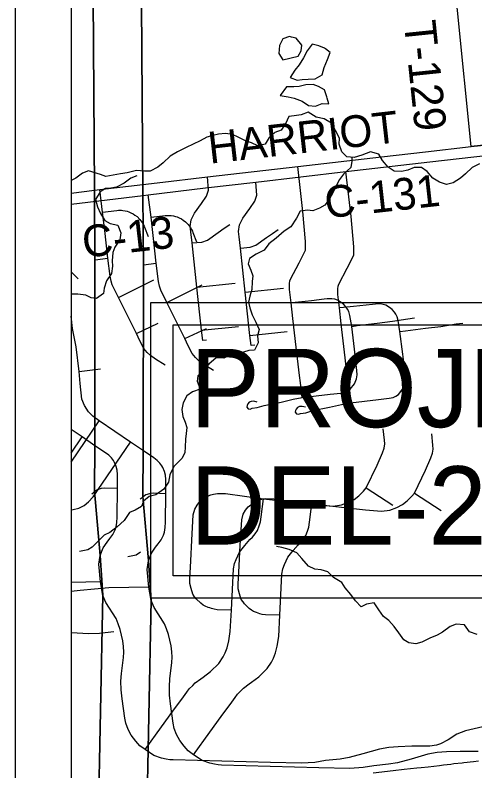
# Model space of a CAD drawing. Extents: x -38.2 to 41.9, y -4 to 24.9.
# Drawn here: x 2 to 2.823, y 17.256 to 18.608 of the extents above; entities that cross this region are included whole.
import ezdxf

# ---------------------------------------------------------------- set-up
doc = ezdxf.new("R2010")
doc.units = 0
for name, color, linetype in [('Default', 7, 'Continuous'), ('GM_X_County_Road', 7, 'Continuous'), ('GM_X_County_Road_Text', 7, 'Continuous'), ('GM_X_Interchange_Ramps', 7, 'Continuous'), ('GM_X_Minor_Lake', 7, 'Continuous'), ('GM_X_Minor_River', 7, 'Continuous'), ('GM_X_Minor_River_Text', 7, 'Continuous'), ('GM_X_State_Location', 7, 'Continuous'), ('GM_X_Township_Road', 7, 'Continuous'), ('GM_X_Township_Road_Text', 7, 'Continuous'), ('GM_X_Township_Text', 7, 'Continuous'), ('SH_Border', 7, 'Continuous'), ('SH_Cut_Line', 7, 'Continuous'), ('SH_Data', 7, 'Continuous'), ('SH_Text', 7, 'Continuous')]:
    doc.layers.add(name, color=color, linetype=linetype)

msp = doc.modelspace()

# ---------------------------------------------------------------- linework, layer by layer
at = {"layer": 'Default'}
msp.add_lwpolyline([(2.8287, 17.2735), (2.82, 17.2725), (2.8029, 17.2705), (2.7997, 17.2701), (2.785, 17.2684), (2.7794, 17.2677), (2.7662, 17.2662), (2.759, 17.2654), (2.7387, 17.263), (2.7266, 17.2616), (2.7184, 17.2607), (2.6958, 17.2583), (2.6765, 17.2561), (2.6404, 17.252)], dxfattribs=at)
at = {"layer": 'GM_X_County_Road'}
msp.add_line((2.1, 18.2896), (2.1423, 18.2947), dxfattribs=at)
for points in [[(2.1423, 18.2947), (2.1516, 18.2959), (2.2543, 18.308), (2.3444, 18.3185), (2.5055, 18.3373), (2.6552, 18.3545), (2.734, 18.3635), (2.8156, 18.3728)], [(2.8156, 18.3728), (2.8545, 18.3772), (2.8608, 18.3772), (2.8641, 18.3768), (2.8674, 18.3761), (2.8706, 18.375), (2.8767, 18.3722), (2.8852, 18.3671), (2.9348, 18.3318), (2.9748, 18.3043)]]:
    msp.add_lwpolyline(points, dxfattribs=at)
at = {"layer": 'GM_X_Interchange_Ramps'}
for points in [[(2.1, 20.4515), (2.1, 14.1636), (2.1303, 14.1626), (2.1303, 14.1722), (2.1335, 15.4167), (2.1334, 15.4951), (2.1328, 15.831), (2.1521, 16.6664), (2.1489, 17.073), (2.1485, 17.1357), (2.1484, 17.1455), (2.1486, 17.1556), (2.1569, 17.5704), (2.1549, 17.5972), (2.1521, 17.6416), (2.1422, 17.7563), (2.1427, 17.838), (2.1429, 18.1709), (2.1421, 18.2952), (2.138, 18.8976), (2.1339, 19.396), (2.1223, 20.2725), (2.1124, 20.4526)], [(2.1, 20.4344), (2.1, 14.1575), (2.2168, 14.1534), (2.2168, 14.163), (2.22, 15.4075), (2.2199, 15.4859), (2.2193, 15.8218), (2.2386, 16.6572), (2.2354, 17.0638), (2.235, 17.1266), (2.2349, 17.1363), (2.2351, 17.1464), (2.2434, 17.5612), (2.2414, 17.5881), (2.2386, 17.6324), (2.2287, 17.7471), (2.2291, 17.8288), (2.2294, 18.1617), (2.2286, 18.286), (2.2245, 18.8884), (2.2204, 19.3868), (2.2088, 20.2633), (2.1989, 20.4434)]]:
    msp.add_lwpolyline(points, close=True, dxfattribs=at)
for points in [[(2.1223, 20.2725), (2.1339, 19.396), (2.138, 18.8976), (2.1421, 18.2952), (2.1429, 18.1709), (2.1427, 17.838), (2.1422, 17.7563), (2.1521, 17.6416), (2.1549, 17.5972), (2.1569, 17.5704), (2.1486, 17.1556)], [(2.2088, 20.2633), (2.2204, 19.3868), (2.2245, 18.8884), (2.2286, 18.286), (2.2294, 18.1617), (2.2291, 17.8288), (2.2287, 17.7471), (2.2386, 17.6324), (2.2414, 17.5881), (2.2434, 17.5612), (2.2351, 17.1464)]]:
    msp.add_lwpolyline(points, dxfattribs=at)
at = {"layer": 'GM_X_Minor_Lake'}
for points in [[(2.4947, 18.5687), (2.4909, 18.5697), (2.4791, 18.5656), (2.473, 18.5538), (2.4718, 18.5394), (2.479, 18.528)], [(2.479, 18.528), (2.5063, 18.5344), (2.5117, 18.5438), (2.5132, 18.5541), (2.503, 18.5666), (2.4947, 18.5687)], [(2.5552, 18.5474), (2.5534, 18.5487), (2.5432, 18.5529), (2.5315, 18.5559), (2.5227, 18.5438), (2.5162, 18.5317), (2.5082, 18.5188), (2.5006, 18.5093), (2.4922, 18.4961)], [(2.4922, 18.4961), (2.5043, 18.4919), (2.5138, 18.4926), (2.5241, 18.4937), (2.537, 18.4941), (2.5491, 18.5012), (2.5526, 18.5145), (2.5591, 18.5285), (2.5637, 18.5414), (2.5552, 18.5474)], [(2.5584, 18.4592), (2.5578, 18.4617), (2.5536, 18.4743), (2.5426, 18.48), (2.5331, 18.4838), (2.5202, 18.4835), (2.5081, 18.4805), (2.4986, 18.4794), (2.4853, 18.4798), (2.4739, 18.4639)], [(2.4739, 18.4639), (2.4887, 18.4619), (2.4993, 18.4593), (2.5133, 18.4539), (2.5251, 18.4463), (2.5372, 18.4451), (2.549, 18.4496), (2.5611, 18.4492), (2.5584, 18.4592)]]:
    msp.add_lwpolyline(points, dxfattribs=at)
at = {"layer": 'GM_X_Minor_River'}
for points in [[(2.7593, 18.309), (2.7472, 18.3166), (2.7373, 18.3284), (2.7267, 18.3353), (2.7138, 18.3353), (2.7024, 18.3308), (2.6914, 18.3281), (2.6781, 18.3289), (2.6671, 18.3362), (2.6573, 18.348), (2.6505, 18.359), (2.6357, 18.3636), (2.6201, 18.3576), (2.6068, 18.3534), (2.5935, 18.3542), (2.5844, 18.3637), (2.5799, 18.377), (2.5803, 18.3881), (2.5732, 18.4017), (2.566, 18.4147), (2.5527, 18.4227), (2.5383, 18.4257), (2.5243, 18.4341), (2.5117, 18.4296), (2.4992, 18.4278), (2.4897, 18.4266), (2.484, 18.4134), (2.476, 18.4024), (2.4646, 18.3983), (2.4547, 18.3892), (2.4471, 18.3774), (2.4341, 18.374), (2.4231, 18.3794), (2.4121, 18.3832), (2.3993, 18.3897), (2.389, 18.3947), (2.3761, 18.3962), (2.364, 18.3951), (2.3537, 18.3925), (2.3431, 18.3895), (2.3313, 18.3831), (2.3187, 18.3774), (2.3058, 18.3714), (2.2902, 18.3635), (2.2773, 18.3555), (2.2647, 18.3438), (2.2552, 18.3362), (2.2415, 18.3291), (2.2313, 18.3287), (2.2172, 18.3299), (2.2005, 18.3261), (2.1884, 18.3243), (2.1625, 18.319), (2.1527, 18.3229), (2.1315, 18.3294)], [(2.6024, 18.3537), (2.6026, 18.347), (2.6003, 18.3352), (2.5874, 18.3235), (2.5805, 18.3137), (2.574, 18.3015), (2.569, 18.2913), (2.5618, 18.278), (2.5542, 18.2682), (2.5447, 18.2629), (2.5325, 18.258), (2.523, 18.2588), (2.5101, 18.2573), (2.5036, 18.2448), (2.4933, 18.2293), (2.4815, 18.2217), (2.4671, 18.2088), (2.4538, 18.1986), (2.4458, 18.1876), (2.4313, 18.1805), (2.4195, 18.1729), (2.4172, 18.1631), (2.4214, 18.1517), (2.4251, 18.1418), (2.4243, 18.1312), (2.4232, 18.1171), (2.4201, 18.105), (2.4174, 18.0947), (2.42, 18.0845), (2.4238, 18.0716), (2.4306, 18.0586), (2.4363, 18.0457), (2.4339, 18.0343), (2.4347, 18.0218), (2.4282, 18.0089), (2.4183, 18.0078), (2.4084, 18.0048), (2.3985, 18.0014), (2.3864, 18.0011), (2.3731, 17.9946), (2.3598, 17.9947), (2.3465, 17.9837), (2.3381, 17.9739), (2.3267, 17.9629), (2.3259, 17.9534), (2.3312, 17.939), (2.3171, 17.9341), (2.3072, 17.9269), (2.3007, 17.9144), (2.298, 17.9026), (2.3003, 17.8901), (2.3044, 17.8798), (2.3071, 17.8703), (2.3063, 17.8593), (2.3051, 17.8494), (2.3043, 17.835), (2.3035, 17.8255), (2.2986, 17.8157), (2.2837, 17.8005), (2.2768, 17.7857), (2.2742, 17.7728), (2.2658, 17.76), (2.2517, 17.7501), (2.2399, 17.7471), (2.2296, 17.7388), (2.2262, 17.729), (2.2148, 17.7222), (2.2045, 17.7184), (2.195, 17.704), (2.1828, 17.6926), (2.1695, 17.6824), (2.1596, 17.6775), (2.1379, 17.6565)], [(2.8308, 18.3418), (2.8174, 18.3354), (2.806, 18.324), (2.7965, 18.3161), (2.7836, 18.3078), (2.7718, 18.3051), (2.7593, 18.309)], [(2.1315, 18.3294), (2.1203, 18.3255), (2.1085, 18.3164), (2.1, 18.3122)], [(2.1379, 17.6565), (2.1301, 17.6514), (2.1154, 17.6484)], [(2.5247, 17.6221), (2.5129, 17.6358), (2.5042, 17.6461), (2.4902, 17.6519), (2.4773, 17.6557), (2.4674, 17.6572)], [(2.8265, 17.5001), (2.8129, 17.5047), (2.8038, 17.5173), (2.789, 17.5185), (2.7784, 17.5143), (2.7647, 17.5045), (2.7548, 17.4988), (2.7419, 17.4936), (2.7278, 17.4864), (2.7171, 17.4834), (2.7046, 17.4849), (2.6951, 17.4903), (2.6864, 17.5028), (2.6781, 17.5146), (2.6687, 17.5249), (2.6592, 17.5321), (2.6509, 17.5439), (2.6422, 17.5565), (2.6285, 17.5543), (2.619, 17.5497), (2.6092, 17.5604), (2.6005, 17.5718), (2.5902, 17.5836), (2.5842, 17.5931), (2.5694, 17.6019), (2.5596, 17.6122), (2.5474, 17.6156), (2.536, 17.6172), (2.5247, 17.6221)]]:
    msp.add_lwpolyline(points, dxfattribs=at)
at = {"layer": 'GM_X_Minor_River_Text'}
for points in [[(2.218, 18.3203), (2.2068, 18.3163), (2.195, 18.3072), (2.1813, 18.3004), (2.1715, 18.2985), (2.1616, 18.2978), (2.1521, 18.2917), (2.1441, 18.2781), (2.1475, 18.2652), (2.1528, 18.2534), (2.1607, 18.2405), (2.1702, 18.2351), (2.1835, 18.2325), (2.1891, 18.2188), (2.1872, 18.2059), (2.1781, 18.193), (2.1747, 18.1831), (2.1739, 18.1683), (2.1742, 18.1588), (2.1727, 18.1459), (2.1632, 18.1327), (2.1593, 18.1198), (2.1582, 18.1099), (2.1457, 18.1012), (2.1358, 18.102), (2.1263, 18.1069), (2.1123, 18.1088), (2.1, 18.1089)], [(2.2244, 17.6473), (2.2165, 17.6422), (2.2019, 17.6392)]]:
    msp.add_lwpolyline(points, dxfattribs=at)
at = {"layer": 'GM_X_State_Location'}
for p, q in [((2.2296, 18.1612), (2.2522, 18.1641)), ((2.113, 18.1364), (2.1, 18.149)), ((2.2712, 18.0938), (2.3346, 18.1254)), ((2.4115, 18.1123), (2.4802, 18.1195)), ((2.3034, 18.0293), (2.3424, 18.0477)), ((2.4199, 18.0351), (2.4864, 18.0419)), ((2.1146, 17.9706), (2.1526, 17.9751)), ((2.1, 17.8085), (2.1502, 17.8822)), ((2.7147, 17.7531), (2.7624, 17.7219)), ((2.2237, 17.7425), (2.2289, 17.7465))]:
    msp.add_line(p, q, dxfattribs=at)
for points in [[(2.5999, 17.9147), (2.5973, 17.9409), (2.5954, 17.9539), (2.5895, 18.0052), (2.5833, 18.0559), (2.5803, 18.0843), (2.5775, 18.1082), (2.5771, 18.114), (2.5774, 18.1186), (2.5782, 18.1232), (2.5793, 18.1267), (2.5943, 18.1554), (2.6061, 18.1786), (2.6061, 18.1936), (2.6011, 18.2477), (2.5919, 18.3281)], [(2.4287, 18.0176), (2.4223, 18.017), (2.4199, 18.0351), (2.4115, 18.1123), (2.403, 18.1914), (2.4007, 18.2114), (2.3999, 18.2207), (2.4012, 18.2327), (2.4074, 18.2447), (2.4198, 18.262), (2.4287, 18.2749), (2.4322, 18.2859), (2.4309, 18.3093)], [(2.2522, 18.1641), (2.2468, 18.2138), (2.2431, 18.2463), (2.2381, 18.2867)], [(2.2431, 18.2463), (2.2684, 18.2494), (2.2716, 18.2496), (2.2741, 18.2497), (2.2766, 18.2496), (2.2791, 18.2494), (2.2832, 18.2488), (2.2867, 18.2479), (2.2898, 18.2469), (2.2937, 18.2453), (2.2974, 18.2434), (2.3009, 18.2412), (2.3049, 18.2383), (2.3095, 18.2334), (2.3116, 18.2308), (2.3135, 18.2281), (2.3156, 18.2245), (2.3171, 18.2215), (2.318, 18.2192), (2.3243, 18.2027)], [(2.403, 18.1914), (2.4207, 18.1927), (2.4305, 18.1963), (2.45, 18.2101), (2.4607, 18.2176), (2.4704, 18.2243)], [(2.3547, 17.9724), (2.3376, 17.9833), (2.3289, 17.9897), (2.3225, 17.9956), (2.3168, 18.0024), (2.3097, 18.0162), (2.3034, 18.0293), (2.2712, 18.0938), (2.2604, 18.1162), (2.258, 18.123), (2.2564, 18.1317), (2.2522, 18.1641)], [(2.5236, 17.8979), (2.5321, 17.9006), (2.5623, 17.9066), (2.5841, 17.9115), (2.5999, 17.9147), (2.6501, 17.9206), (2.6689, 17.9228), (2.6764, 17.9242), (2.681, 17.9263), (2.6859, 17.9296), (2.6938, 17.9394), (2.6974, 17.9481), (2.6985, 17.9552), (2.6981, 17.9632), (2.6936, 18.0013), (2.6885, 18.042), (2.6852, 18.0617), (2.6833, 18.0685), (2.6813, 18.0728), (2.6789, 18.0767), (2.6745, 18.0813), (2.67, 18.0849), (2.6629, 18.089), (2.6582, 18.0904), (2.6533, 18.0913), (2.6485, 18.0915), (2.645, 18.0911), (2.6391, 18.0906), (2.6168, 18.0879), (2.6051, 18.0867), (2.5874, 18.0848), (2.5803, 18.0843)], [(2.2294, 17.8283), (2.2064, 17.8443), (2.1502, 17.8822), (2.139, 17.8905), (2.1312, 17.8985), (2.1243, 17.9094), (2.1195, 17.921), (2.1166, 17.949), (2.1146, 17.9706), (2.109, 18.0144), (2.1025, 18.0475), (2.1, 18.0693)], [(2.6885, 18.042), (2.6986, 18.0435), (2.7343, 18.0478), (2.7618, 18.0511), (2.7889, 18.0555), (2.8009, 18.057)], [(2.5194, 17.9066), (2.5134, 17.908), (2.5089, 17.9078), (2.5051, 17.9062), (2.5029, 17.9033), (2.5014, 17.9007), (2.5012, 17.8975), (2.5034, 17.8946), (2.5071, 17.8942), (2.5103, 17.8956), (2.5198, 17.8967), (2.5236, 17.8979)], [(2.4736, 17.5345), (2.448, 17.5352), (2.4422, 17.5361), (2.4375, 17.5373), (2.4348, 17.5383), (2.4321, 17.5394), (2.4264, 17.5413), (2.4226, 17.5436), (2.4187, 17.5466), (2.4106, 17.5546), (2.4077, 17.5583), (2.4046, 17.5629), (2.4012, 17.573), (2.3993, 17.5819), (2.3988, 17.5901), (2.4009, 17.6227), (2.4029, 17.6596), (2.4053, 17.705), (2.408, 17.715), (2.4121, 17.7224), (2.4169, 17.7285), (2.4244, 17.7345), (2.4266, 17.7355), (2.4321, 17.739), (2.4368, 17.7408), (2.4416, 17.742), (2.4485, 17.7433), (2.4629, 17.7429), (2.5309, 17.7338), (2.6269, 17.7229), (2.6555, 17.7206), (2.6702, 17.7227), (2.6831, 17.7274), (2.6928, 17.7326), (2.7011, 17.7389), (2.71, 17.7474), (2.7147, 17.7531), (2.7341, 17.7937), (2.7435, 17.8159), (2.7469, 17.8242), (2.7478, 17.8318), (2.7473, 17.8387), (2.7452, 17.8587)], [(2.1, 17.7229), (2.104, 17.7234), (2.114, 17.7258), (2.1238, 17.7309), (2.1311, 17.7373), (2.1397, 17.7462), (2.2064, 17.8443)], [(2.2388, 17.6319), (2.244, 17.6457), (2.251, 17.656), (2.2561, 17.6625), (2.2613, 17.6695), (2.2653, 17.6779), (2.2673, 17.6832), (2.2686, 17.6912), (2.269, 17.7007), (2.2698, 17.7519), (2.2699, 17.7772), (2.2691, 17.7851), (2.2675, 17.7914), (2.2644, 17.7986), (2.2624, 17.802), (2.259, 17.8066), (2.2543, 17.8115), (2.2484, 17.816), (2.2294, 17.8283)], [(2.2698, 17.7519), (2.2471, 17.7526), (2.2402, 17.7519), (2.2337, 17.7496), (2.2289, 17.7465)], [(2.3189, 17.2849), (2.3481, 17.3255), (2.3688, 17.3535), (2.3878, 17.3792), (2.3934, 17.3874), (2.3981, 17.3934), (2.4044, 17.3999), (2.4088, 17.4043), (2.4187, 17.4115), (2.4228, 17.4148), (2.4358, 17.4244), (2.4508, 17.4391), (2.4588, 17.4507), (2.4622, 17.458), (2.4656, 17.4672), (2.469, 17.4793), (2.4715, 17.4965), (2.4736, 17.5345), (2.4774, 17.6082), (2.4792, 17.6176), (2.4817, 17.6252), (2.4878, 17.6381), (2.4975, 17.6504), (2.5066, 17.6605), (2.511, 17.6649), (2.516, 17.6709), (2.52, 17.677), (2.5232, 17.685), (2.5254, 17.6921), (2.5268, 17.7012), (2.5309, 17.7338)], [(2.2436, 17.5606), (2.239, 17.585), (2.2364, 17.6166), (2.2388, 17.6319)], [(2.239, 17.585), (2.1679, 17.5838), (2.1161, 17.5787), (2.1, 17.5767)], [(2.8284, 17.291), (2.8161, 17.2908), (2.7963, 17.2909), (2.7718, 17.29), (2.7552, 17.2888), (2.7386, 17.2858), (2.7086, 17.2772), (2.6843, 17.2707), (2.6677, 17.268), (2.642, 17.2652), (2.6225, 17.2621), (2.599, 17.2606), (2.5432, 17.2616), (2.369, 17.2666), (2.3632, 17.2667), (2.3566, 17.2678), (2.3485, 17.2699), (2.3347, 17.2745), (2.3189, 17.2849), (2.3097, 17.2917), (2.3023, 17.3001), (2.2944, 17.3105), (2.2886, 17.3212), (2.2845, 17.3321), (2.2825, 17.3414), (2.2778, 17.376), (2.2762, 17.3918), (2.2759, 17.4072), (2.2765, 17.421), (2.2804, 17.4497), (2.2809, 17.4593), (2.2805, 17.4692), (2.2794, 17.4796), (2.2744, 17.5), (2.271, 17.5102), (2.2673, 17.5193), (2.249, 17.5483), (2.2436, 17.5606)], [(2.1, 17.5035), (2.1321, 17.502), (2.1512, 17.5022), (2.1766, 17.5055)]]:
    msp.add_lwpolyline(points, dxfattribs=at)
at = {"layer": 'GM_X_Township_Road'}
for p, q in [((2.1432, 18.1704), (2.1658, 18.1733)), ((2.1847, 18.103), (2.2481, 18.1346)), ((2.325, 18.1215), (2.3937, 18.1287)), ((2.2169, 18.0385), (2.256, 18.0569)), ((2.3334, 18.0443), (2.3999, 18.0511)), ((2.1, 17.8242), (2.1199, 17.8535)), ((2.1372, 17.7517), (2.1424, 17.7557)), ((2.6283, 17.7623), (2.6759, 17.7311)), ((2.1525, 17.5942), (2.1, 17.5933))]:
    msp.add_line(p, q, dxfattribs=at)
for points in [[(2.8156, 18.3728), (2.7912, 18.6162), (2.7771, 18.7553), (2.7607, 18.8984)], [(2.9748, 18.3043), (2.9348, 18.3318), (2.8852, 18.3671), (2.8767, 18.3722), (2.8706, 18.375), (2.8674, 18.3761), (2.8641, 18.3768), (2.8608, 18.3772), (2.8545, 18.3772), (2.8156, 18.3728)], [(2.5134, 17.9239), (2.5108, 17.9501), (2.5089, 17.9631), (2.503, 18.0143), (2.4968, 18.0651), (2.4938, 18.0935), (2.491, 18.1174), (2.4907, 18.1232), (2.4909, 18.1278), (2.4917, 18.1324), (2.4928, 18.1359), (2.5079, 18.1646), (2.5196, 18.1878), (2.5196, 18.2028), (2.5146, 18.2569), (2.5055, 18.3373)], [(2.3422, 18.0268), (2.3358, 18.0262), (2.3334, 18.0443), (2.325, 18.1215), (2.3165, 18.2006), (2.3143, 18.2206), (2.3134, 18.2299), (2.3147, 18.2419), (2.3209, 18.2539), (2.3333, 18.2712), (2.3422, 18.284), (2.3458, 18.2951), (2.3444, 18.3185)], [(2.1658, 18.1733), (2.1603, 18.223), (2.1566, 18.2555), (2.1516, 18.2959)], [(2.1566, 18.2555), (2.1819, 18.2586), (2.1851, 18.2588), (2.1876, 18.2589), (2.1901, 18.2588), (2.1926, 18.2586), (2.1967, 18.2579), (2.2002, 18.2571), (2.2034, 18.2561), (2.2072, 18.2545), (2.2109, 18.2526), (2.2144, 18.2504), (2.2184, 18.2475), (2.223, 18.2426), (2.2251, 18.24), (2.227, 18.2373), (2.2291, 18.2337), (2.2306, 18.2307), (2.2315, 18.2284), (2.2378, 18.2119)], [(2.3165, 18.2006), (2.3342, 18.2019), (2.344, 18.2055), (2.3635, 18.2192), (2.3742, 18.2268), (2.3839, 18.2334)], [(2.2682, 17.9816), (2.2511, 17.9925), (2.2424, 17.9989), (2.236, 18.0047), (2.2303, 18.0116), (2.2232, 18.0254), (2.2169, 18.0385), (2.1847, 18.103), (2.1739, 18.1254), (2.1716, 18.1322), (2.1699, 18.1409), (2.1658, 18.1733)], [(2.4371, 17.9071), (2.4456, 17.9098), (2.4759, 17.9158), (2.4977, 17.9207), (2.5134, 17.9239), (2.5636, 17.9298), (2.5825, 17.932), (2.5899, 17.9334), (2.5945, 17.9355), (2.5994, 17.9388), (2.6073, 17.9486), (2.611, 17.9573), (2.612, 17.9644), (2.6116, 17.9724), (2.6071, 18.0105), (2.6021, 18.0512), (2.5987, 18.0709), (2.5968, 18.0777), (2.5948, 18.0819), (2.5924, 18.0858), (2.588, 18.0905), (2.5835, 18.0941), (2.5765, 18.0981), (2.5717, 18.0996), (2.5668, 18.1005), (2.562, 18.1007), (2.5585, 18.1003), (2.5527, 18.0998), (2.5304, 18.0971), (2.5186, 18.0959), (2.5009, 18.094), (2.4938, 18.0935)], [(2.6021, 18.0512), (2.6121, 18.0527), (2.6478, 18.0569), (2.6753, 18.0603), (2.7024, 18.0647), (2.7145, 18.0662)], [(2.433, 17.9158), (2.4269, 17.9172), (2.4224, 17.917), (2.4186, 17.9154), (2.4164, 17.9125), (2.4149, 17.9099), (2.4147, 17.9066), (2.417, 17.9038), (2.4206, 17.9034), (2.4238, 17.9048), (2.4333, 17.9059), (2.4371, 17.9071)], [(2.1429, 17.8375), (2.1199, 17.8535), (2.1, 17.8669)], [(2.3871, 17.5437), (2.3615, 17.5444), (2.3558, 17.5453), (2.3511, 17.5465), (2.3483, 17.5475), (2.3456, 17.5486), (2.3399, 17.5505), (2.3362, 17.5528), (2.3322, 17.5558), (2.3241, 17.5638), (2.3212, 17.5675), (2.3181, 17.5721), (2.3147, 17.5822), (2.3128, 17.5911), (2.3123, 17.5993), (2.3144, 17.6319), (2.3164, 17.6688), (2.3188, 17.7142), (2.3216, 17.7242), (2.3256, 17.7316), (2.3304, 17.7377), (2.3379, 17.7437), (2.3401, 17.7447), (2.3456, 17.7482), (2.3503, 17.7499), (2.3551, 17.7512), (2.362, 17.7525), (2.3765, 17.7521), (2.4444, 17.743), (2.5405, 17.7321), (2.5691, 17.7298), (2.5837, 17.7319), (2.5966, 17.7366), (2.6063, 17.7418), (2.6147, 17.748), (2.6235, 17.7566), (2.6283, 17.7623), (2.6476, 17.8029), (2.6571, 17.8251), (2.6604, 17.8334), (2.6613, 17.841), (2.6608, 17.8478), (2.6587, 17.8679)], [(2.1524, 17.6411), (2.1575, 17.6549), (2.1645, 17.6651), (2.1697, 17.6717), (2.1748, 17.6787), (2.1788, 17.6871), (2.1808, 17.6924), (2.1821, 17.7004), (2.1826, 17.7099), (2.1834, 17.7611), (2.1834, 17.7864), (2.1826, 17.7942), (2.181, 17.8005), (2.1779, 17.8078), (2.1759, 17.8112), (2.1725, 17.8158), (2.1678, 17.8207), (2.1619, 17.8252), (2.1429, 17.8375)], [(2.1834, 17.7611), (2.1606, 17.7618), (2.1537, 17.7611), (2.1473, 17.7588), (2.1424, 17.7557)], [(2.2324, 17.2941), (2.2616, 17.3347), (2.2823, 17.3627), (2.3013, 17.3884), (2.3069, 17.3966), (2.3116, 17.4026), (2.3179, 17.409), (2.3224, 17.4135), (2.3322, 17.4207), (2.3363, 17.424), (2.3494, 17.4336), (2.3644, 17.4483), (2.3723, 17.4599), (2.3757, 17.4672), (2.3791, 17.4764), (2.3825, 17.4885), (2.385, 17.5057), (2.3871, 17.5437), (2.3909, 17.6174), (2.3927, 17.6268), (2.3952, 17.6344), (2.4013, 17.6473), (2.4111, 17.6595), (2.4201, 17.6697), (2.4245, 17.6741), (2.4295, 17.6801), (2.4335, 17.6862), (2.4368, 17.6942), (2.4389, 17.7013), (2.4404, 17.7104), (2.4444, 17.743)], [(2.1571, 17.5698), (2.1525, 17.5942), (2.1499, 17.6258), (2.1524, 17.6411)], [(2.852, 17.3384), (2.8056, 17.3275), (2.79, 17.3215), (2.7747, 17.3117), (2.7609, 17.3045), (2.7536, 17.3021), (2.742, 17.3002), (2.7296, 17.3), (2.7098, 17.3001), (2.6853, 17.2992), (2.6687, 17.298), (2.6521, 17.295), (2.6222, 17.2864), (2.5978, 17.2799), (2.5812, 17.2772), (2.5555, 17.2744), (2.536, 17.2713), (2.5125, 17.2698), (2.4568, 17.2708), (2.2825, 17.2758), (2.2768, 17.2759), (2.2702, 17.277), (2.262, 17.279), (2.2483, 17.2837), (2.2324, 17.2941), (2.2232, 17.3009), (2.2158, 17.3093), (2.2079, 17.3197), (2.2021, 17.3304), (2.198, 17.3413), (2.196, 17.3506), (2.1913, 17.3852), (2.1898, 17.401), (2.1894, 17.4164), (2.1901, 17.4302), (2.1939, 17.4589), (2.1944, 17.4685), (2.194, 17.4783), (2.1929, 17.4887), (2.1879, 17.5092), (2.1845, 17.5194), (2.1808, 17.5285), (2.1625, 17.5575), (2.1571, 17.5698)]]:
    msp.add_lwpolyline(points, dxfattribs=at)
at = {"layer": 'GM_X_Township_Road_Text'}
msp.add_line((2.1, 18.2699), (2.2288, 18.2855), dxfattribs=at)
msp.add_lwpolyline([(2.2288, 18.2855), (2.2381, 18.2867), (2.3408, 18.2988), (2.4309, 18.3093), (2.5919, 18.3281), (2.7417, 18.3453), (2.8205, 18.3543), (2.902, 18.3636)], dxfattribs=at)
at = {"layer": 'SH_Border'}
msp.add_lwpolyline([(2.243, 18.0941), (4.0919, 18.0941), (4.0919, 17.5648), (2.243, 17.5648)], close=True, dxfattribs=at)
at = {"layer": 'SH_Cut_Line'}
msp.add_lwpolyline([(2.1103, 20.9), (2.1, 20.9), (2.1, 14.1636), (2.1303, 14.1626), (2.1303, 14.1722), (2.1335, 15.4167), (2.1334, 15.4951), (2.1328, 15.831), (2.1521, 16.6664), (2.1489, 17.073), (2.1485, 17.1357), (2.1484, 17.1455), (2.1486, 17.1556), (2.1569, 17.5704), (2.1549, 17.5972), (2.1521, 17.6416), (2.1422, 17.7563), (2.1427, 17.838), (2.1429, 18.1709), (2.1421, 18.2952), (2.138, 18.8976), (2.1339, 19.396), (2.1223, 20.2725), (2.1124, 20.4526)], close=True, dxfattribs=at)
msp.add_lwpolyline([(8.9, 20.9), (2.1103, 20.9), (2.1124, 20.4526), (2.1223, 20.2725), (2.1339, 19.396), (2.138, 18.8976), (2.1421, 18.2952), (2.1429, 18.1709), (2.1427, 17.838), (2.1422, 17.7563), (2.1521, 17.6416), (2.1549, 17.5972), (2.1569, 17.5704), (2.1486, 17.1556)], dxfattribs=at)
at = {"layer": 'SH_Data'}
for p, q in [((2, 21), (2, 14)), ((2.1, 20.9), (2.1, 14.1))]:
    msp.add_line(p, q, dxfattribs=at)
at = {"layer": 'SH_Text'}
msp.add_lwpolyline([(2.283, 18.0541), (4.0916, 18.0541), (4.0916, 17.6048), (2.283, 17.6048)], close=True, dxfattribs=at)

# ---------------------------------------------------------------- texts
at = {"layer": 'GM_X_County_Road_Text'}
for s, rotation, p in [('HARRIOT', 6.5109, (2.3484, 18.3421)), ('C-131', 6.3399, (2.5568, 18.2443))]:
    msp.add_text(s, height=0.05682, rotation=rotation, dxfattribs=at).set_placement(p)
at = {"layer": 'GM_X_Township_Road_Text'}
msp.add_text('T-129', height=0.05682, rotation=275.9062, dxfattribs=at).set_placement((2.6953, 18.5956))
at = {"layer": 'GM_X_Township_Text'}
msp.add_text('C-13', height=0.05682, rotation=6.53, dxfattribs=at).set_placement((2.1232, 18.1737))
at = {"layer": 'SH_Text'}
for s, p in [('PROJECT LOCATION', (2.313, 17.8709)), ('DEL-257, SLM 1.25 ', (2.313, 17.6609))]:
    msp.add_text(s, height=0.14, dxfattribs=at).set_placement(p)

doc.saveas('drawing.dxf')
